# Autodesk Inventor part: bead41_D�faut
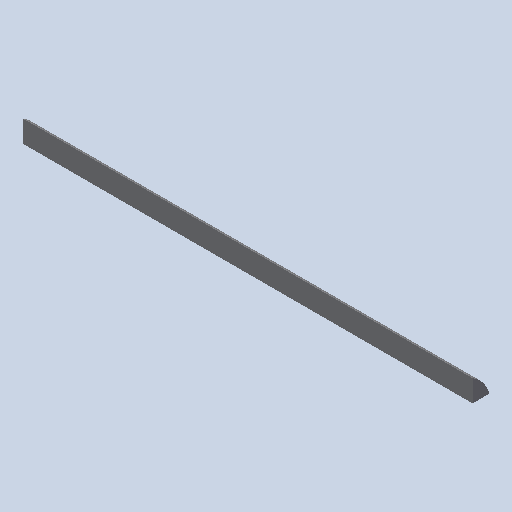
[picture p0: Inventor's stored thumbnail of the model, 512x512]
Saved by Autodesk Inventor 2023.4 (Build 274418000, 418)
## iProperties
Created: 2011-01
Part Number: bead41_D�faut
Document SubType Name: Modeling
Designer: eric
Density: 1 g/cm^3
Mass: 0.07456 g
Surface Area: 2.41867 cm^2
Volume: 0.07456 cm^3
Material: Générique
Appearance: Par défaut
Author: eric
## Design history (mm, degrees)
feature "Base1"
node "Corps solides"
node "Corps surfaciques"
node "Solide1"
